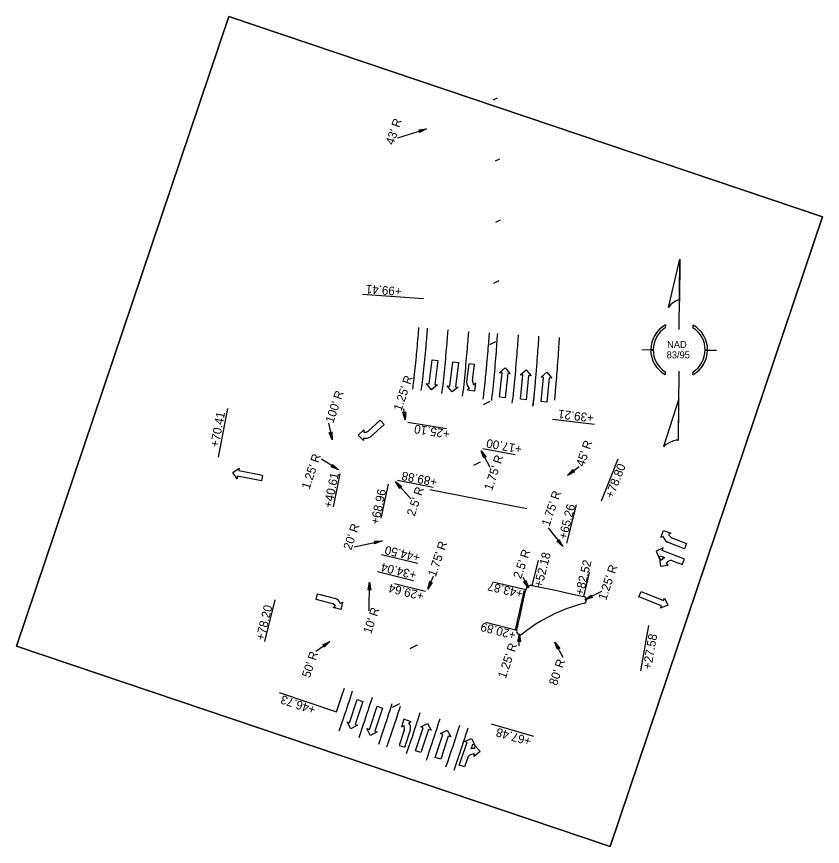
# Model space of a CAD drawing. Extents: x 1623150 to 1624004, y 886654 to 888237.
# Drawn here: x 1623538.9 to 1624003.7, y 887758 to 888236.6 of the extents above; entities that cross this region are included whole.
import ezdxf

# ---------------------------------------------------------------- set-up
doc = ezdxf.new("R2010")
doc.units = 0
for name, color, linetype in [('Default', 7, 'Continuous'), ('Exist Utilities Power Joint Use Telephone CELL', 7, 'Continuous'), ('P_RDY_Dimension', 7, 'Continuous'), ('P_RDY_Lane_Line', 7, 'Continuous'), ('P_RDY_Terminator_Cell', 7, 'Continuous'), ('Sheet_Plan_CELL', 7, 'Continuous'), ('Sheet_Sticker_Incomplete_CELL', 7, 'Continuous')]:
    doc.layers.add(name, color=color, linetype=linetype)

msp = doc.modelspace()

# ---------------------------------------------------------------- linework, layer by layer
at = {"layer": 'Default'}
msp.add_open_spline([(1623768.07, 888026.42), (1623768.19, 888027.6), (1623768.64, 888031.61), (1623769.4, 888039.06), (1623769.92, 888044.57), (1623770.59, 888052.05), (1623770.92, 888056.05), (1623771.02, 888057.23)], degree=3, dxfattribs=at)
at = {"layer": 'Exist Utilities Power Joint Use Telephone CELL'}
msp.add_lwpolyline([(1623836.4, 887908.43), (1623840.02, 887907.69), (1623849.82, 887905.72), (1623859.58, 887903.56), (1623866.08, 887902.06)], dxfattribs=at)
for centre, radius, start, end in [((1623835.75, 887905.25), 3.25, 78.515, 168.0861), ((1623865.62, 887900.11), 2, 284.3476, 76.9371), ((1623889.54, 887806.62), 94.5, 104.3476, 128.6112), ((1623829.32, 887882.02), 2, 166.8699, 308.6112)]:
    msp.add_arc(centre, radius, start, end, dxfattribs=at)
msp.add_open_spline([(1623827.37, 887882.48), (1623827.45, 887882.84), (1623828.22, 887886.11), (1623829.72, 887892.69), (1623831.41, 887900.42), (1623832.31, 887904.68), (1623832.57, 887905.92)], degree=3, dxfattribs=at)
at = {"layer": 'P_RDY_Dimension'}
for p, q in [((1623758.87, 888166.73), (1623775.39, 888171.89)), ((1623773.57, 888073.79), (1623738.43, 888076.23)), ((1623655.41, 887982.41), (1623660.69, 888010.62)), ((1623763.14, 888004.07), (1623762.35, 888010.45)), ((1623718.84, 888002.04), (1623720.92, 887992.5)), ((1623764.55, 888002.64), (1623786.87, 887999.07)), ((1623872.19, 888001.3), (1623848.03, 888004.17)), ((1623807.89, 887987.45), (1623826.52, 887984)), ((1623806.91, 887986.18), (1623811.9, 887976.8)), ((1623724.54, 887975.15), (1623714.72, 887981.32)), ((1623885.73, 887981.24), (1623876.11, 887957.03)), ((1623863.36, 887976.95), (1623856.65, 887971.94)), ((1623725.31, 887972.78), (1623721.43, 887953.9)), ((1623766.33, 887958.36), (1623757.5, 887968.36)), ((1623758.64, 887969.17), (1623779.21, 887965.19)), ((1623753.18, 887966.94), (1623748.99, 887947.25)), ((1623833.17, 887952.66), (1623777.27, 887963.58)), ((1623861.65, 887955.03), (1623856.07, 887932.95)), ((1623845.46, 887941.76), (1623853.91, 887931.05)), ((1623733.72, 887930.84), (1623749.7, 887934.16)), ((1623749.41, 887926.34), (1623770.39, 887921.36)), ((1623836.4, 887908.43), (1623840.03, 887922.84)), ((1623747.03, 887916.53), (1623767.85, 887911.37)), ((1623866.08, 887902.06), (1623869.48, 887915.92)), ((1623776.19, 887906.43), (1623779.38, 887913.77)), ((1623830.92, 887913.23), (1623834.17, 887907.2)), ((1623742.21, 887893.83), (1623742.48, 887910.37)), ((1623756.9, 887909.67), (1623774.85, 887905.14)), ((1623832.57, 887905.92), (1623813.59, 887910.44)), ((1623876.26, 887904.92), (1623866.73, 887900.21)), ((1623682.17, 887876.25), (1623688.06, 887900.17)), ((1623827.37, 887882.48), (1623809.65, 887887.1)), ((1623903.37, 887885.41), (1623898.77, 887859.22)), ((1623828.76, 887873.65), (1623829.09, 887880.57)), ((1623711.53, 887870.62), (1623719.64, 887876.21)), ((1623854.21, 887866.94), (1623849.39, 887875.81)), ((1623690.34, 887846.81), (1623723.49, 887835.63)), ((1623812.62, 887828.62), (1623837.12, 887821.61))]:
    msp.add_line(p, q, dxfattribs=at)
msp.add_lwpolyline([(1623538.9, 887873.47), (1623881.25, 887757.98), (1624003.74, 888121.1), (1623661.39, 888236.59)], close=True, dxfattribs=at)
at = {"layer": 'P_RDY_Lane_Line'}
for p, q in [((1623814.05, 888188.55), (1623816.27, 888189.65)), ((1623815.23, 888153.32), (1623817.74, 888154.56)), ((1623815.28, 888118.04), (1623818.08, 888119.42)), ((1623814.18, 888082.75), (1623817.29, 888084.29)), ((1623811.92, 888047.5), (1623815.35, 888049.2)), ((1623776.92, 888024.71), (1623778.58, 888038.61)), ((1623778.58, 888038.61), (1623781.86, 888038.22)), ((1623781.86, 888038.22), (1623780.2, 888024.31)), ((1623788.86, 888023.52), (1623790.52, 888037.42)), ((1623790.52, 888037.42), (1623793.8, 888037.03)), ((1623793.8, 888037.03), (1623792.14, 888023.13)), ((1623799.7, 888036.34), (1623798.44, 888025.87)), ((1623802.98, 888035.95), (1623799.7, 888036.34)), ((1623801.89, 888026.87), (1623802.98, 888035.95)), ((1623817.42, 888031.17), (1623820.81, 888034)), ((1623818.91, 888031.03), (1623817.42, 888031.17)), ((1623817.53, 888017.09), (1623818.91, 888031.03)), ((1623820.81, 888034), (1623823.69, 888030.55)), ((1623822.19, 888030.7), (1623820.81, 888016.77)), ((1623823.69, 888030.55), (1623822.19, 888030.7)), ((1623829.4, 888030.03), (1623832.8, 888032.86)), ((1623832.8, 888032.86), (1623835.67, 888029.41)), ((1623841.42, 888028.65), (1623844.82, 888031.48)), ((1623844.82, 888031.48), (1623847.69, 888028.03)), ((1623830.9, 888029.88), (1623829.4, 888030.03)), ((1623829.51, 888015.95), (1623830.9, 888029.88)), ((1623834.18, 888029.55), (1623832.8, 888015.62)), ((1623835.67, 888029.41), (1623834.18, 888029.55)), ((1623842.92, 888028.5), (1623841.42, 888028.65)), ((1623841.53, 888014.57), (1623842.92, 888028.5)), ((1623846.2, 888028.18), (1623844.82, 888014.24)), ((1623847.69, 888028.03), (1623846.2, 888028.18)), ((1623778.23, 888021.38), (1623775.43, 888024.88)), ((1623775.43, 888024.88), (1623776.92, 888024.71)), ((1623781.68, 888024.14), (1623778.23, 888021.38)), ((1623780.2, 888024.31), (1623781.68, 888024.14)), ((1623790.17, 888020.19), (1623787.37, 888023.7)), ((1623787.37, 888023.7), (1623788.86, 888023.52)), ((1623793.63, 888022.95), (1623790.17, 888020.19)), ((1623792.14, 888023.13), (1623793.63, 888022.95)), ((1623800.12, 888022.19), (1623798.95, 888021.28)), ((1623798.95, 888021.28), (1623803.31, 888020.7)), ((1623803.9, 888025.16), (1623802.73, 888024.25)), ((1623803.31, 888020.7), (1623803.9, 888025.16)), ((1623820.81, 888016.77), (1623817.53, 888017.09)), ((1623832.8, 888015.62), (1623829.51, 888015.95)), ((1623808.32, 888012.8), (1623812.12, 888014.69)), ((1623844.82, 888014.24), (1623841.53, 888014.57)), ((1623741.85, 887997.67), (1623748.62, 888003.83)), ((1623748.62, 888003.83), (1623750.84, 888001.39)), ((1623736, 887995.26), (1623739.3, 887998.33)), ((1623739.3, 887998.33), (1623739.23, 887996.84)), ((1623750.84, 888001.39), (1623743.04, 887994.29)), ((1623739, 887992.04), (1623736, 887995.26)), ((1623739.07, 887993.52), (1623739, 887992.04)), ((1623802.7, 887977.83), (1623806.6, 887979.76)), ((1623663.61, 887973.69), (1623667.32, 887976.23)), ((1623666.11, 887970.04), (1623663.61, 887973.69)), ((1623667.32, 887976.23), (1623667.03, 887974.75)), ((1623667.03, 887974.75), (1623680.77, 887972.06)), ((1623666.4, 887971.52), (1623666.11, 887970.04)), ((1623680.14, 887968.83), (1623666.4, 887971.52)), ((1623680.77, 887972.06), (1623680.14, 887968.83)), ((1623910.56, 887936.15), (1623912.14, 887940.25)), ((1623912.14, 887940.25), (1623916.34, 887938.63)), ((1623911.92, 887936.74), (1623910.56, 887936.15)), ((1623916.34, 887938.63), (1623914.98, 887938.05)), ((1623916.87, 887936.05), (1623925.37, 887932.66)), ((1623911.88, 887930.12), (1623907.83, 887928.34)), ((1623911.32, 887928.73), (1623911.88, 887930.12)), ((1623924.14, 887929.59), (1623914.35, 887933.51)), ((1623925.37, 887932.66), (1623924.14, 887929.59)), ((1623907.83, 887928.34), (1623909.55, 887924.27)), ((1623909.55, 887924.27), (1623910.11, 887925.66)), ((1623910.11, 887925.66), (1623912.75, 887924.61)), ((1623924.15, 887923.63), (1623911.32, 887928.73)), ((1623910.96, 887923.07), (1623909.76, 887923.97)), ((1623909.76, 887923.97), (1623910.38, 887919.58)), ((1623910.38, 887919.58), (1623914.77, 887920.2)), ((1623914.77, 887920.2), (1623913.61, 887921.09)), ((1623916.94, 887922.95), (1623922.93, 887920.56)), ((1623922.93, 887920.56), (1623924.15, 887923.63)), ((1623711.75, 887900.37), (1623712.55, 887903.57)), ((1623712.55, 887903.57), (1623722.78, 887901.03)), ((1623897.91, 887901.85), (1623899.13, 887904.92)), ((1623910.93, 887896.69), (1623897.91, 887901.85)), ((1623899.13, 887904.92), (1623912.14, 887899.76)), ((1623912.14, 887899.76), (1623912.7, 887901.16)), ((1623912.7, 887901.16), (1623914.48, 887897.11)), ((1623720.63, 887898.16), (1623711.75, 887900.37)), ((1623721.51, 887895.68), (1623722.78, 887896.44)), ((1623725.63, 887898.15), (1623726.9, 887898.92)), ((1623726.9, 887898.92), (1623725.88, 887894.64)), ((1623914.48, 887897.11), (1623910.37, 887895.3)), ((1623910.37, 887895.3), (1623910.93, 887896.69)), ((1623725.88, 887894.64), (1623721.51, 887895.68)), ((1623765.95, 887872.06), (1623770.19, 887874.16)), ((1623731.02, 887829.34), (1623735.44, 887842.62)), ((1623738.57, 887841.58), (1623734.15, 887828.3)), ((1623735.44, 887842.62), (1623738.57, 887841.58)), ((1623755.66, 887838.24), (1623760.03, 887840.4)), ((1623742.39, 887825.5), (1623746.81, 887838.79)), ((1623749.94, 887837.75), (1623745.52, 887824.46)), ((1623746.81, 887838.79), (1623749.94, 887837.75)), ((1623725.06, 887824.67), (1623727.67, 887832.38)), ((1623731.64, 887825.81), (1623729.59, 887829.81)), ((1623729.59, 887829.81), (1623731.02, 887829.34)), ((1623762.36, 887831.28), (1623760.9, 887827.03)), ((1623766.52, 887829.85), (1623762.36, 887831.28)), ((1623765.19, 887829.19), (1623766.52, 887829.85)), ((1623735.57, 887827.82), (1623731.64, 887825.81)), ((1623734.15, 887828.3), (1623735.57, 887827.82)), ((1623736.43, 887820.83), (1623739.04, 887828.55)), ((1623743.01, 887821.98), (1623740.97, 887825.98)), ((1623740.97, 887825.98), (1623742.39, 887825.5)), ((1623745.52, 887824.46), (1623746.94, 887823.99)), ((1623747.81, 887817), (1623750.41, 887824.71)), ((1623762.53, 887824.96), (1623759.65, 887816.27)), ((1623760.9, 887827.03), (1623762.22, 887827.69)), ((1623762.78, 887815.24), (1623766.1, 887825.25)), ((1623769.05, 887813.16), (1623773.45, 887826.45)), ((1623772.03, 887826.92), (1623775.96, 887828.94)), ((1623773.45, 887826.45), (1623772.03, 887826.92)), ((1623776.58, 887825.41), (1623772.18, 887812.12)), ((1623775.96, 887828.94), (1623778.01, 887824.94)), ((1623778.01, 887824.94), (1623776.58, 887825.41)), ((1623783.4, 887823.09), (1623787.33, 887825.1)), ((1623787.33, 887825.1), (1623789.38, 887821.1)), ((1623746.94, 887823.99), (1623743.01, 887821.98)), ((1623752.54, 887815.4), (1623755.15, 887823.11)), ((1623780.42, 887809.33), (1623784.82, 887822.61)), ((1623784.82, 887822.61), (1623783.4, 887823.09)), ((1623787.95, 887821.58), (1623783.55, 887808.29)), ((1623789.38, 887821.1), (1623787.95, 887821.58)), ((1623797.31, 887818.42), (1623801.3, 887820.31)), ((1623801.3, 887820.31), (1623803.26, 887816.35)), ((1623759.65, 887816.27), (1623762.78, 887815.24)), ((1623763.91, 887811.56), (1623766.52, 887819.28)), ((1623775.28, 887807.73), (1623777.89, 887815.44)), ((1623794.21, 887804.89), (1623798.73, 887817.93)), ((1623798.73, 887817.93), (1623797.31, 887818.42)), ((1623801.85, 887816.84), (1623800.91, 887814.15)), ((1623803.26, 887816.35), (1623801.85, 887816.84)), ((1623803.26, 887814.5), (1623803.35, 887816)), ((1623803.35, 887816), (1623806.27, 887812.66)), ((1623772.18, 887812.12), (1623769.05, 887813.16)), ((1623806.27, 887812.66), (1623802.93, 887809.75)), ((1623802.93, 887809.75), (1623803.01, 887811.2)), ((1623783.55, 887808.29), (1623780.42, 887809.33)), ((1623791.25, 887801.87), (1623793.99, 887810.01)), ((1623799.44, 887809.9), (1623797.32, 887803.81)), ((1623797.32, 887803.81), (1623794.21, 887804.89))]:
    msp.add_line(p, q, dxfattribs=at)
for centre, radius, start, end in [((1622735.12, 888167.2), 1042.5, 351.97333, 352.23859), ((1622735.12, 888167.2), 1047.5, 351.97333, 352.23859), ((1623803.68, 888026.04), 5.25, 181.8283, 227.14), ((1623805.12, 888026.47), 3.27, 173.1522, 222.8104), ((1622735.12, 888167.2), 1059.5, 351.97333, 352.23859), ((1622735.12, 888167.2), 1071.5, 351.97333, 352.23859), ((1622735.12, 888167.2), 1083.5, 351.97333, 352.23859), ((1622735.12, 888167.2), 1088.5, 351.97333, 352.23859), ((1622735.12, 888167.2), 1100.5, 351.97333, 352.23859), ((1623739.65, 888000.08), 3.27, 262.628, 312.2862), ((1623740.14, 887998.65), 5.25, 258.2984, 303.6101), ((1623917, 887938.02), 5.25, 194.2333, 239.545), ((1623918.07, 887939.08), 3.27, 198.5629, 248.2211), ((1623914.67, 887920.63), 4.43, 115.844, 146.7226), ((1623917.32, 887918.65), 4.43, 115.7502, 146.6037), ((1623916.63, 887920.44), 2.52, 82.9283, 119.2403), ((1623720.77, 887896.19), 5.25, 22.0414, 67.353), ((1623719.85, 887895), 3.27, 26.3709, 76.0291), ((1622735.12, 888167.2), 1042.5, 341.45481, 342.24612), ((1622735.12, 888167.2), 1047.5, 341.35887, 342.24612), ((1622735.12, 888167.2), 1059.5, 341.35887, 342.24612), ((1622735.12, 888167.2), 1071.5, 341.35887, 342.24612), ((1622735.12, 888167.2), 1076.5, 341.35887, 342.24612), ((1622735.12, 888167.2), 1088.5, 341.35887, 342.24612), ((1622735.12, 888167.2), 1100.5, 341.35887, 342.24612), ((1623759.44, 887825.99), 3.27, 341.6685, 31.3267), ((1623760.94, 887826.13), 5.25, 350.3446, 35.6562), ((1622735.12, 888167.2), 1112.5, 340.93499, 342.24612), ((1622735.12, 888167.2), 1117.5, 341.35887, 342.24612), ((1623801.54, 887808.49), 2.52, 109.9422, 146.2542), ((1623802.44, 887806.8), 4.43, 82.5788, 113.4323), ((1623802.67, 887810.1), 4.43, 82.46, 113.3386)]:
    msp.add_arc(centre, radius, start, end, dxfattribs=at)
for points, degree in [([(1623773.02, 888025.74), (1623773.29, 888028.23), (1623773.83, 888033.2), (1623774.58, 888040.67), (1623775.27, 888048.14), (1623775.73, 888053.53), (1623775.97, 888056.43), (1623776, 888056.83)], 3), ([(1623784.91, 888024.12), (1623785.18, 888026.64), (1623785.7, 888031.67), (1623786.43, 888039.23), (1623787.1, 888046.79), (1623787.55, 888052.36), (1623787.79, 888055.4), (1623787.83, 888055.93)], 3), ([(1623796.8, 888022.5), (1623797.07, 888025.05), (1623797.6, 888030.14), (1623798.32, 888037.78), (1623799, 888045.43), (1623799.46, 888051.18), (1623799.71, 888054.38), (1623799.76, 888055.03)], 3), ([(1623808.69, 888020.88), (1623808.84, 888022.35), (1623809.37, 888027.4), (1623810.24, 888036.61), (1623810.88, 888043.92), (1623811.36, 888049.95), (1623811.62, 888053.33), (1623811.68, 888054.14)], 3), ([(1623813.65, 888020.2), (1623813.9, 888022.79), (1623814.39, 888027.97), (1623815.07, 888035.74), (1623815.69, 888043.52), (1623816.13, 888049.54), (1623816.37, 888052.98), (1623816.43, 888053.82)], 3), ([(1623825.54, 888018.58), (1623825.79, 888021.2), (1623826.3, 888026.44), (1623826.98, 888034.29), (1623827.62, 888042.15), (1623828.08, 888048.4), (1623828.33, 888052.02), (1623828.39, 888053.02)], 3), ([(1623837.43, 888016.96), (1623837.67, 888019.61), (1623838.17, 888024.9), (1623838.83, 888032.85), (1623839.44, 888040.8), (1623839.89, 888047.27), (1623840.14, 888051.1), (1623840.21, 888052.28)], 3), ([(1623849.32, 888015.34), (1623849.56, 888018.02), (1623850.05, 888023.37), (1623850.71, 888031.4), (1623851.32, 888039.44), (1623851.78, 888046.16), (1623852.03, 888050.19), (1623852.12, 888051.55)], 3), ([(1623836.72, 888011.87), (1623837.01, 888013.96), (1623837.26, 888015.76), (1623837.43, 888016.96)], 2), ([(1623836.89, 888012.17), (1623837.07, 888013.77), (1623837.25, 888015.36), (1623837.43, 888016.96)], 2), ([(1623826.78, 887883.24), (1623826.82, 887883.41), (1623827.53, 887886.49), (1623828.98, 887892.86), (1623830.62, 887900.32), (1623831.48, 887904.36), (1623831.7, 887905.43)], 3)]:
    msp.add_open_spline(points, degree=degree, dxfattribs=at)
at = {"layer": 'P_RDY_Terminator_Cell'}
for points in [[(1623770.86, 888171.29), (1623775.39, 888171.89), (1623771.31, 888169.77), (1623771.62, 888170.71)], [(1623763.36, 888008.63), (1623763.14, 888004.07), (1623761.79, 888008.46), (1623762.66, 888007.99)], [(1623720.72, 887997.06), (1623720.92, 887992.5), (1623719.17, 887996.75), (1623720.08, 887996.36)], [(1623808.34, 887981.85), (1623806.91, 887986.18), (1623809.74, 887982.56), (1623808.76, 887982.7)], [(1623721.14, 887978.2), (1623724.54, 887975.15), (1623720.28, 887976.88), (1623721.19, 887977.25)], [(1623860.72, 887974.01), (1623856.65, 887971.94), (1623859.8, 887975.29), (1623859.82, 887974.31)], [(1623759.9, 887964.47), (1623757.5, 887968.36), (1623761.1, 887965.5), (1623760.11, 887965.4)], [(1623851.73, 887935.06), (1623853.91, 887931.05), (1623850.48, 887934.11), (1623851.46, 887934.15)], [(1623745.13, 887934), (1623749.7, 887934.16), (1623745.43, 887932.46), (1623745.83, 887933.36)], [(1623778.7, 887910.25), (1623776.19, 887906.43), (1623777.26, 887910.9), (1623777.77, 887910.05)], [(1623832.72, 887911.52), (1623834.17, 887907.2), (1623831.32, 887910.8), (1623832.3, 887910.67)], [(1623741.63, 887905.88), (1623742.48, 887910.37), (1623743.21, 887905.83), (1623742.42, 887906.42)], [(1623871.11, 887901.51), (1623866.73, 887900.21), (1623870.43, 887902.93), (1623870.27, 887901.96)], [(1623828.1, 887876.11), (1623829.09, 887880.57), (1623829.67, 887876.01), (1623828.9, 887876.62)], [(1623715.5, 887874.3), (1623719.64, 887876.21), (1623716.37, 887872.99), (1623716.39, 887873.97)], [(1623850.86, 887871.49), (1623849.39, 887875.81), (1623852.25, 887872.22), (1623851.28, 887872.34)]]:
    msp.add_lwpolyline(points, close=True, dxfattribs=at)
at = {"layer": 'Sheet_Plan_CELL'}
msp.add_lwpolyline([(1624003.74, 888121.1), (1623881.25, 887757.98), (1623538.9, 887873.47), (1623661.39, 888236.59)], close=True, dxfattribs=at)
at = {"layer": 'Sheet_Sticker_Incomplete_CELL'}
for p, q in [((1623914.93, 888068.88), (1623921.41, 888096.65)), ((1623921.17, 888056.12), (1623921.43, 888096.65)), ((1623921.43, 888096.65), (1623921.28, 888072.28)), ((1623921.43, 888096.65), (1623921.41, 888096.65)), ((1623921.43, 888096.65), (1623921.41, 888096.65)), ((1623921.28, 888072.28), (1623921.28, 888072.97)), ((1623921.28, 888072.97), (1623921.29, 888072.96)), ((1623913.13, 888058.71), (1623913.12, 888057.08)), ((1623913.13, 888058.73), (1623913.13, 888058.71)), ((1623929.26, 888056.96), (1623929.27, 888058.6)), ((1623899.5, 888044.52), (1623906.1, 888044.47)), ((1623906.1, 888044.47), (1623904.7, 888044.48)), ((1623904.7, 888044.48), (1623906.1, 888044.47)), ((1623936.09, 888044.28), (1623942.69, 888044.24)), ((1623936.09, 888044.28), (1623937.49, 888044.27)), ((1623937.5, 888044.27), (1623936.09, 888044.28)), ((1623912.96, 888031.78), (1623912.94, 888030.15)), ((1623920.76, 887992.1), (1623921.02, 888032.04)), ((1623929.08, 888030.05), (1623929.1, 888031.69)), ((1623929.09, 888030.04), (1623929.08, 888030.05)), ((1623920.9, 888016.1), (1623912.11, 887988.58)), ((1623920.77, 887992.11), (1623920.9, 888016.1))]:
    msp.add_line(p, q, dxfattribs=at)
for radius, start, end in [(16.4, 119.0636, 240.1952), (15, 122.1326, 237.1262), (16.4, 299.1498, 60.109), (15, 302.23, 57.0288), (15, 359.6294, 57.0288), (16.4, 359.6294, 60.109), (16.4, 179.6294, 240.1952), (15, 179.6294, 237.1262)]:
    msp.add_arc((1623921.1, 888044.38), radius, start, end, dxfattribs=at)
for centre, major_axis, ratio, start_param, end_param in [((1623918.05, 888070.59), (3.21, 2.43), 0.261723, 6.225794, 8.917625), ((1623921.1, 888044.38), (0.11, 16.42), 0.998737, 0.514018, 1.570796), ((1623921.1, 888044.38), (0.1, 15.02), 0.998737, 0.567287, 1.570796), ((1623921.1, 888044.38), (0.11, 16.42), 0.998737, 3.657116, 4.712389), ((1623921.1, 888044.38), (0.1, 15.02), 0.998737, 3.71058, 4.712389), ((1623916.44, 887990.19), (4.32, 1.91), 0.225493, 6.280036, 9.220301)]:
    msp.add_ellipse(centre, major_axis=major_axis, ratio=ratio, start_param=start_param, end_param=end_param, dxfattribs=at)

# ---------------------------------------------------------------- texts
at = {"layer": 'P_RDY_Dimension'}
for s, rotation, p in [("43' R", 71.3589, (1623756.32, 888162.23)), ('+99.41', 176.0346, (1623761.15, 888080.48)), ("1.25' R", 71.3589, (1623760.84, 888008.72)), ("100' R", 71.3589, (1623721.59, 888001.77)), ('+70.41', 79.3998, (1623655.39, 887987.91)), ('+39.21', 173.2073, (1623872.12, 888007.44)), ('+25.10', 170.9177, (1623789.11, 887998.05)), ('+17.00', 169.5068, (1623830.73, 887989.33)), ("45' R", 71.3589, (1623866.19, 887976.61)), ("1.25' R", 71.3589, (1623707.81, 887963.57)), ("1.75' R", 71.3589, (1623813.11, 887962.87)), ('+78.80', 68.3419, (1623882.83, 887958.36)), ('+40.61', 78.3942, (1623720.72, 887952.85)), ('+89.88', 169.0494, (1623781.81, 887970.34)), ('+68.96', 77.988, (1623747.84, 887943.28)), ("2.5' R", 71.3589, (1623768.51, 887948.06)), ("1.75' R", 71.3589, (1623846.31, 887942.26)), ('+65.26', 75.8422, (1623856.19, 887934.71)), ("20' R", 71.3589, (1623731.92, 887928.55)), ('+44.50', 166.6414, (1623772.06, 887926.74)), ("1.75' R", 71.3589, (1623780.71, 887913.1)), ("2.5' R", 71.3589, (1623829.9, 887911.97)), ('+52.18', 75.8422, (1623842.02, 887906.91)), ('+34.04', 166.0867, (1623769.93, 887916.66)), ('+82.52', 76.2066, (1623865.74, 887902.47)), ("1.25' R", 71.3589, (1623878.94, 887899.56)), ('+29.64', 165.8533, (1623774.27, 887904.5)), ('+43.87', 166.608, (1623831.45, 887905.85)), ('+78.20', 76.1718, (1623681.59, 887876.46)), ("10' R", 71.3589, (1623743.43, 887880.22)), ('+20.89', 165.3893, (1623827.32, 887881.99)), ('+27.58', 80.0419, (1623904.95, 887859.8)), ("1.25' R", 71.3589, (1623821.05, 887854.41)), ("50' R", 71.3589, (1623708.04, 887854.87)), ("80' R", 71.3589, (1623850.5, 887850.43)), ('+46.73', 161.3589, (1623711.85, 887838.72)), ('+67.48', 164.0387, (1623836.2, 887820.73))]:
    msp.add_text(s, height=5, rotation=rotation, dxfattribs=at).set_placement(p)
at = {"layer": 'Sheet_Sticker_Incomplete_CELL'}
for s, p in [('NAD', (1623914.15, 888045.48)), ('83/95', (1623913.9, 888039.48))]:
    msp.add_text(s, height=4, dxfattribs=at).set_placement(p)

doc.saveas('drawing.dxf')
